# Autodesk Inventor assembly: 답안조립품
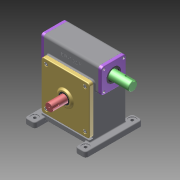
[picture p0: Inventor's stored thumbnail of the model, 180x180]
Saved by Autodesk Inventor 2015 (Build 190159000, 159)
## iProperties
Created: 2025-06
Part Number: 답안조립품
Document SubType Name: Assembly
Designer: User
Author: User
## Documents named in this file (13)
- C:\Users\User\Desktop\750603V1011\답안조립품.iam
- C:\Users\User\Desktop\750603V1011\가져온 구성요소\6각 구멍붙이 볼트 M8x20\6각 구멍붙이 볼트 M8x20.ipt
- C:\Users\User\Desktop\750603V1011\가져온 구성요소\깊은 홈 볼 베어링 6206\깊은 홈 볼 베어링 6206.ipt
- C:\Users\User\Desktop\750603V1011\가져온 구성요소\깊은 홈 볼 베어링 6209\깊은 홈 볼 베어링 6209.ipt
- C:\Users\User\Desktop\750603V1011\가져온 구성요소\뒷커버\뒷커버.ipt
- C:\Users\User\Desktop\750603V1011\본체.ipt
- C:\Users\User\Desktop\750603V1011\가져온 구성요소\앞커버\앞커버.ipt
- C:\Users\User\Desktop\750603V1011\가져온 구성요소\오일 실 30 42 7\오일 실 30 42 7.ipt
- C:\Users\User\Desktop\750603V1011\가져온 구성요소\오일 실 35 55 11\오일 실 35 55 11.ipt
- C:\Users\User\Desktop\750603V1011\가져온 구성요소\웜 샤프트\웜 샤프트.ipt
- C:\Users\User\Desktop\750603V1011\가져온 구성요소\웜 휠 커버\웜 휠 커버.ipt
- C:\Users\User\Desktop\750603V1011\가져온 구성요소\웜 휠\웜 휠.ipt
- C:\Users\User\Desktop\750603V1011\가져온 구성요소\6각 구멍붙이 볼트 M6x12\6각 구멍붙이 볼트 M6x12.ipt
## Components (12 placed, 2 different names)
1. 6각 구멍붙이 볼트 M8x20:1
2. 6각 구멍붙이 볼트 M8x20:2
3. 6각 구멍붙이 볼트 M8x20:3
4. 6각 구멍붙이 볼트 M8x20:4
5. 6각 구멍붙이 볼트 M6x12:9
6. 6각 구멍붙이 볼트 M6x12:10
7. 6각 구멍붙이 볼트 M6x12:11
8. 6각 구멍붙이 볼트 M6x12:12
9. 6각 구멍붙이 볼트 M6x12:13
10. 6각 구멍붙이 볼트 M6x12:14
11. 6각 구멍붙이 볼트 M6x12:15
12. 6각 구멍붙이 볼트 M6x12:16
## Component patterns: 구성요소 패턴 6:2 (2 elements)
